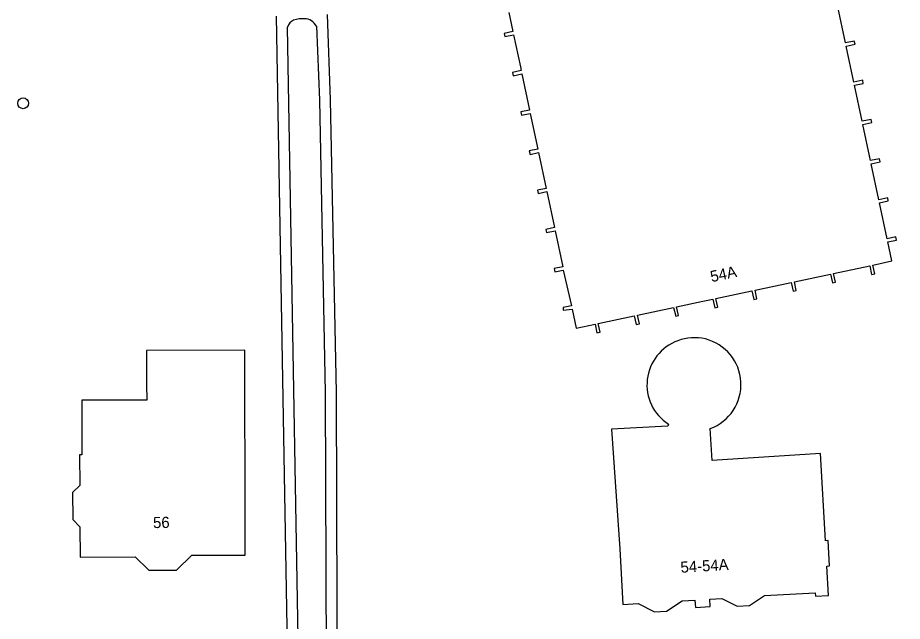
# Model space of a CAD drawing. Extents: x 161772 to 163123, y 383092 to 383917.
# Drawn here: x 161951 to 162030.4, y 383652.6 to 383706.8 of the extents above; entities that cross this region are included whole.
import ezdxf

# ---------------------------------------------------------------- set-up
doc = ezdxf.new("R2010")
doc.units = 0
for name, color, linetype in [('IMGEO_Boom', 7, 'Continuous'), ('IMGEO_Erf', 7, 'Continuous'), ('IMGEO_Pand', 7, 'Continuous'), ('IMGEO_Pand_nummerreeks', 7, 'Continuous'), ('IMGEO_Waterloop', 7, 'Continuous')]:
    doc.layers.add(name, color=color, linetype=linetype)

msp = doc.modelspace()

# ---------------------------------------------------------------- linework, layer by layer
at = {"layer": 'IMGEO_Boom'}
msp.add_circle((161951.538, 383699.071), 0.489, dxfattribs=at)
at = {"layer": 'IMGEO_Erf'}
for points in [[(162076.03, 383713.168), (162081.29, 383637.92), (162050.945, 383636.267), (162037.939, 383635.325), (162033.007, 383636.416), (162032.552, 383636.481), (162000, 383634.927), (161995.375, 383634.706), (161994.874, 383634.661), (161990.043, 383634.37), (161989.536, 383634.344), (161982.69, 383634.025), (161979.782, 383634.174), (161979.655, 383673.111), (161979.131, 383699.377), (161978.844, 383707.033)], [(161974.241, 383706.883), (161975.565, 383631.408)]]:
    msp.add_lwpolyline(points, dxfattribs=at)
at = {"layer": 'IMGEO_Pand'}
for points in [[(161995.117, 383707.226), (161995.483, 383705.51), (161994.7, 383705.343), (161994.762, 383705.052), (161995.545, 383705.219), (161996.159, 383702.336), (161996.231, 383701.999), (161995.456, 383701.834), (161995.518, 383701.545), (161996.293, 383701.71), (161996.986, 383698.456), (161996.194, 383698.287), (161996.257, 383697.994), (161997.048, 383698.163), (161997.73, 383694.961), (161996.955, 383694.796), (161997.023, 383694.475), (161997.799, 383694.64), (161998.482, 383691.431), (161997.691, 383691.263), (161997.753, 383690.969), (161998.545, 383691.137), (161999.231, 383687.916), (161998.445, 383687.748), (161998.507, 383687.454), (161999.294, 383687.622), (161999.981, 383684.397), (161999.194, 383684.229), (161999.256, 383683.935), (162000, 383684.094), (162000.732, 383680.872), (162000, 383680.717), (162000, 383680.495), (162000.794, 383680.58), (162001.156, 383678.881), (162002.858, 383679.243), (162003.027, 383678.446), (162003.321, 383678.511), (162003.152, 383679.305), (162006.37, 383679.989), (162006.539, 383679.195), (162006.837, 383679.258), (162006.668, 383680.053), (162009.888, 383680.738), (162010.11, 383679.962), (162010.352, 383680.007), (162010.183, 383680.8), (162012.526, 383681.299), (162013.426, 383681.49), (162013.594, 383680.698), (162013.873, 383680.763), (162013.706, 383681.55), (162016.942, 383682.238), (162017.11, 383681.448), (162017.39, 383681.516), (162017.224, 383682.298), (162020.469, 383682.988), (162020.637, 383682.199), (162020.916, 383682.263), (162020.749, 383683.047), (162023.988, 383683.736), (162024.155, 383682.949), (162024.439, 383683.01), (162024.272, 383683.796), (162027.508, 383684.484), (162027.675, 383683.701), (162027.954, 383683.761), (162027.788, 383684.543), (162029.501, 383684.908), (162029.139, 383686.613), (162029.922, 383686.781), (162029.86, 383687.071), (162029.078, 383686.904), (162028.391, 383690.139), (162029.171, 383690.305), (162029.121, 383690.573), (162028.334, 383690.406), (162027.649, 383693.632), (162028.431, 383693.798), (162028.373, 383694.093), (162027.587, 383693.926), (162026.9, 383697.162)], [(162026.9, 383697.162), (162027.685, 383697.329), (162027.624, 383697.615), (162026.839, 383697.449), (162026.152, 383700.687), (162026.929, 383700.852), (162026.879, 383701.133), (162026.093, 383700.966), (162025.407, 383704.197), (162026.187, 383704.362), (162026.127, 383704.654), (162025.345, 383704.488), (162024.656, 383707.738)], [(161956.806, 383672.412), (161956.817, 383667.493), (161956.607, 383667.493), (161956.614, 383664.756), (161955.978, 383664.118), (161955.984, 383661.701), (161956.638, 383661.05), (161956.644, 383658.324), (161961.602, 383658.335), (161962.811, 383657.132), (161965.313, 383657.138), (161966.663, 383658.494), (161971.468, 383658.505), (161971.456, 383663.505), (161971.431, 383674.375), (161971.425, 383676.903), (161962.614, 383676.882), (161962.621, 383673.809), (161962.625, 383672.425), (161956.806, 383672.412)], [(162009.445, 383670.262), (162009.383, 383670.079), (162004.33, 383669.805), (162005.079, 383659.056), (162005.365, 383654.064), (162006.732, 383654.143), (162008.183, 383653.412), (162009.268, 383653.474), (162010.675, 383654.398), (162011.821, 383654.464), (162011.859, 383653.804), (162013.186, 383653.88), (162013.147, 383654.553), (162014.238, 383654.616), (162015.623, 383653.919), (162016.73, 383653.982), (162018.07, 383654.861), (162022.614, 383655.122), (162022.632, 383654.811), (162023.798, 383654.878), (162023.648, 383657.509), (162023.905, 383657.524), (162023.774, 383659.802), (162023.554, 383659.789), (162023.105, 383667.629), (162013.368, 383667.006), (162013.186, 383669.861)]]:
    msp.add_lwpolyline(points, dxfattribs=at)
for centre, radius, start, end in [((162011.792, 383673.601), 4.413, 77.29787, 110.03299), ((162011.739, 383673.818), 4.214, 290.08142, 75.95238), ((162011.726, 383673.797), 4.207, 110.09991, 237.1693)]:
    msp.add_arc(centre, radius, start, end, dxfattribs=at)
at = {"layer": 'IMGEO_Waterloop'}
for points in [[(161977.875, 383705.994), (161978.125, 383699.348), (161978.648, 383673.099), (161978.778, 383633.217), (161982.688, 383633.017), (161989.585, 383633.338), (161990.026, 383633.364), (161995.222, 383634.319), (161995.699, 383634.327), (162000.019, 383634.533), (162032.406, 383636.08), (162033.023, 383636.028), (162037.662, 383634.755), (162037.854, 383634.702), (162037.964, 383634.71), (162050.985, 383635.624), (162081.979, 383637.312), (162076.673, 383713.22), (162075.968, 383720.946), (162062.408, 383719.768), (162060.997, 383725.905), (162059.9, 383731.347), (162059.975, 383731.695), (162060.018, 383731.868)], [(162098.153, 383633.06), (162056.434, 383632.498), (162038.981, 383631.935), (162038.646, 383631.9), (162038.538, 383631.893), (162038.085, 383631.841), (162037.786, 383631.807), (162033.604, 383631.33), (162033.24, 383631.288), (162033.106, 383631.273), (162032.687, 383631.304), (161999.979, 383629.548), (161995.647, 383629.316), (161995.095, 383629.341), (161994.555, 383629.366), (161990.691, 383629.543), (161989.867, 383629.581), (161988.564, 383629.651), (161976.558, 383632.225), (161975.265, 383705.909)]]:
    msp.add_lwpolyline(points, dxfattribs=at)
for centre, radius, start, end in [((161976.173, 383705.655), 0.943, 112.43503, 164.34401), ((161976.677, 383703.839), 2.823, 87.5311, 107.83324), ((161976.793, 383705.521), 1.138, 56.86683, 89.70055), ((161975.897, 383704.559), 2.444, 35.96272, 51.59953)]:
    msp.add_arc(centre, radius, start, end, dxfattribs=at)

# ---------------------------------------------------------------- texts
at = {"layer": 'IMGEO_Pand_nummerreeks'}
for s, rotation, p in [('54A', 12.00347, (162013.318, 383683.001)), ('56', 0.69954, (161963.202, 383660.924)), ('54-54A', 3.50995, (162010.563, 383656.908))]:
    msp.add_text(s, height=1, rotation=rotation, dxfattribs=at).set_placement(p)

doc.saveas('drawing.dxf')
